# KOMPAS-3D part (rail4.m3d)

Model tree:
1. X Axis
2. Y Axis
3. Z Axis
4. Origin  (labels: D:\Program Files\ASCON\KOMPAS-3D V10\Sys\GRAPHIC_EN.LYT; Rail 04)
     Wall Thickness 1 = 1; Wall Thickness 2 = 1; Distance 1 = 50; Distance 2 = 10

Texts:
  Rail 04
  Three Point Plane
  Plane at Angle
  Line and Point Plane
  Axis through Two Vertices
  Axis of Feature
  Axis of Conical Surface
  Axis through Edge
  Trim by Surface
  Trim by Sketch
  Feature with No History
  Intersection Axis of Two Planes
  Two Line Plane
  Line and Face Plane
  Bend by line
  Hole in sheet body
  Cut in sheet body
  Point in CM
  Linear Dimension from Line to Point
  Surface Finish Symbol
  Geometric Tolerance Symbol
  Leader #1
  Leader #2
  Leader #3
  Shape Deviations and Datum
  Node point number
  Mark of coordination axis
  Node point designation
  Mark/Reference designation with leader
  Mark/reference designation on line
  Mark/Reference designation without leader
  LR4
